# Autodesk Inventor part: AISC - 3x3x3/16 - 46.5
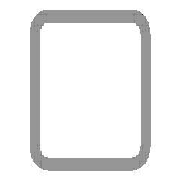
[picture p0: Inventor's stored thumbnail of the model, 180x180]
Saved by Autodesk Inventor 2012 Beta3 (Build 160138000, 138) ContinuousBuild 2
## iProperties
_CCFamilyMember: 9
_CCFamilyDisplayName: ANSI AISC (Square) - Tube
_FrameMemberDoc: Frame Member File
_Version: 15.0.0
_GetPNFromCC: 1
Created: 2011-01
Part Number: AISC - 3x3x3/16 - 46.5
Material: Steel, Mild
Description: Tube
Document SubType Name: Modeling
Standard: ANSI
Designer: Beta-8540w
Standards Organization: ANSI
Language: en-US
Size Designation: 3x3x3/16
Categories: <MemberInstance><Categories><Category DisplayName="Structural Shapes" InternalName="089c4875-fa83-4c05-b084-43b9cc11f5ed" Mnemonic="GRDR"><CategoryParameter Dis
Stock Number: 3x3x3/16
Density: 7.86 g/cm^3
IsCustomPart: 1
G_L: 46.500 in
G_W: 3.000 in
G_H: 3.000 in
+863F2453-9C01-4A8D-87B5-7D7AE1104EF9+CUTDETAIL1: Notch
Author: Beta-8540w
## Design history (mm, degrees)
node "Start plane"
node "End plane"
sketch "Sketch"
  geometry: L1 (-38.1, -28.575)-(-38.1, 28.575); L2 (-28.575, 38.1)-(28.575, 38.1); L3 (38.1, 28.575)-(38.1, -28.575); L4 (28.575, -38.1)-(-28.575, -38.1); L5 (-28.575, 33.337)-(28.575, 33.338); L6 (33.338, 28.575)-(33.338, -28.575); L7 (28.575, -33.337)-(-28.575, -33.338); L8 (-33.338, -28.575)-(-33.338, 28.575); L9 (0, 56.102)-(0, -56.102) reference; L10 (-56.102, 0)-(56.102, 0) reference; A1 r 9.525 centre (-28.575, -28.575) between (-38.1, -28.575) and (-28.575, -38.1); A2 r 9.525 centre (-28.575, 28.575) between (-28.575, 38.1) and (-38.1, 28.575); A3 r 9.525 centre (28.575, 28.575) between (38.1, 28.575) and (28.575, 38.1); A4 r 9.525 centre (28.575, -28.575) between (28.575, -38.1) and (38.1, -28.575); A5 r 4.763 centre (-28.575, 28.575) between (-28.575, 33.337) and (-33.338, 28.575); A6 r 4.763 centre (28.575, 28.575) between (33.338, 28.575) and (28.575, 33.338); A7 r 4.763 centre (28.575, -28.575) between (28.575, -33.337) and (33.338, -28.575); A8 r 4.763 centre (-28.575, -28.575) between (-33.338, -28.575) and (-28.575, -33.338)
  constraints: 16 end point, 16 point on circle, 8 centre point, 8 tangent, 4 parallel, 3 equal radius, 2 perpendicular, 7 other
  dimensions: "d10" = 76.2 distance between parallel lines of L2 L4 (= G_H); "d11" = 76.2 distance between parallel lines of L1 L3 (= G_W); "d12" = 4.7625 distance between parallel lines of L3 L6 (= G_T); "d15" = 38.1 distance between parallel lines of L2 L10 (= 0.5 x d10); "d16" = 38.1 distance between parallel lines of L9 L3 (= 0.5 x d11); "d17" = 9.525 radius of A1 (= G_IR)
extrude "Body" new body sketch "Sketch" stored distance "d3" = 1181.1 (= G_L); taper "d4" = 0 deg
node "Driven Length"
  sketch "Sketch3"
    geometry: L1 (0, 0)-(10, 0) reference
    constraints: 2 end point, 1 horizontal
  workplane "Work Plane3"
  sketch "Sketch4"
    geometry: L1 (-2, 38.1)-(12, 38.1) reference; L2 (-2, 1219.2)-(12, 1219.2) reference
    dimensions: "d19" = 1181.1 distance between parallel lines of L1 L2 (derived)
workplane "Work Plane4"
split "Split1"
workplane "Work Plane5"
workplane "Work Plane6"
workplane "Work Plane7"
sketch "Sketch5"
  geometry: L1 (-38.1, -28.575)-(-38.1, 28.575); L2 (-28.575, 38.1)-(28.575, 38.1); L3 (38.1, 28.575)-(38.1, -28.575); L4 (28.575, -38.1)-(-28.575, -38.1); L5 (-28.575, 33.337)-(28.575, 33.338); L6 (33.338, 28.575)-(33.338, -28.575); L7 (28.575, -33.337)-(-28.575, -33.338); L8 (-33.338, -28.575)-(-33.338, 28.575); A1 r 9.525 centre (-28.575, -28.575) between (-38.1, -28.575) and (-28.575, -38.1); A2 r 9.525 centre (-28.575, 28.575) between (-28.575, 38.1) and (-38.1, 28.575); A3 r 9.525 centre (28.575, 28.575) between (38.1, 28.575) and (28.575, 38.1); A4 r 9.525 centre (28.575, -28.575) between (28.575, -38.1) and (38.1, -28.575); A5 r 4.763 centre (-28.575, 28.575) between (-28.575, 33.337) and (-33.338, 28.575); A6 r 4.763 centre (28.575, 28.575) between (33.338, 28.575) and (28.575, 33.338); A7 r 4.763 centre (28.575, -28.575) between (28.575, -33.337) and (33.338, -28.575); A8 r 4.763 centre (-28.575, -28.575) between (-33.338, -28.575) and (-28.575, -33.338)
  constraints: 16 end point, 16 point on circle, 8 centre point
extrude "Extrusion2" cut sketch "Sketch5" stored distance "d20" = 3.302; taper "d21" = 0 deg
body "Solid1"
other parameters: "G_W" = 76.2 [user parameter; used in 1 equation term], "G_H" = 76.2 [user parameter; used in 1 equation term], "G_T" = 4.7625 [user parameter; used in 1 equation term], "G_IR" = 9.525 [user parameter; used in 1 equation term], "G_L" = 1181.1 (= d19) [user parameter; used in 1 equation term], "G_OFFSET_START" = -38.1 [user parameter; used in 1 equation term], "G_OFFSET_END" = 0 [user parameter; used in 1 equation term], "d13" = 38.1 (= -G_OFFSET_START), "d14" = 1219.2 (= G_OFFSET_END + B_L), "B_L" = 1219.2 [user parameter; used in 1 equation term], "d18" = 90 deg
